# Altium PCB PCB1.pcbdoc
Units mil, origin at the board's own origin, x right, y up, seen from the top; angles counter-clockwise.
Board outline 5106.1 x 2904.45 mil, 2 copper layers (Top Layer, Bottom Layer); 73 components, 114 nets, 374 pads, 0 vias.
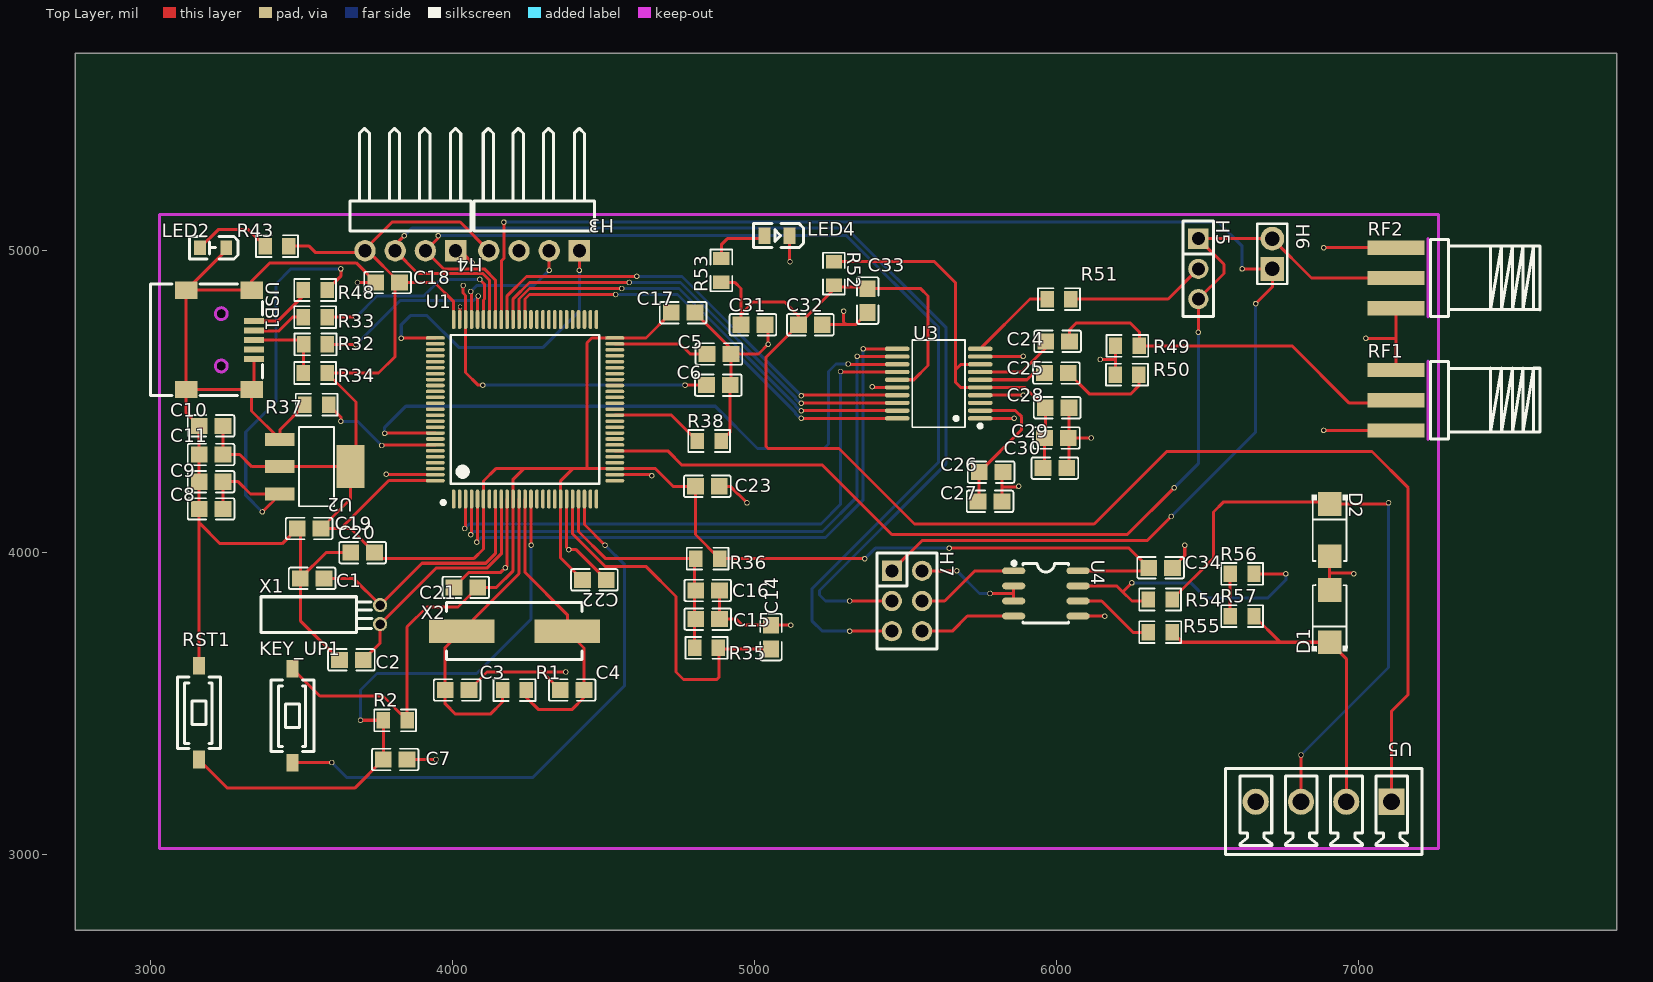
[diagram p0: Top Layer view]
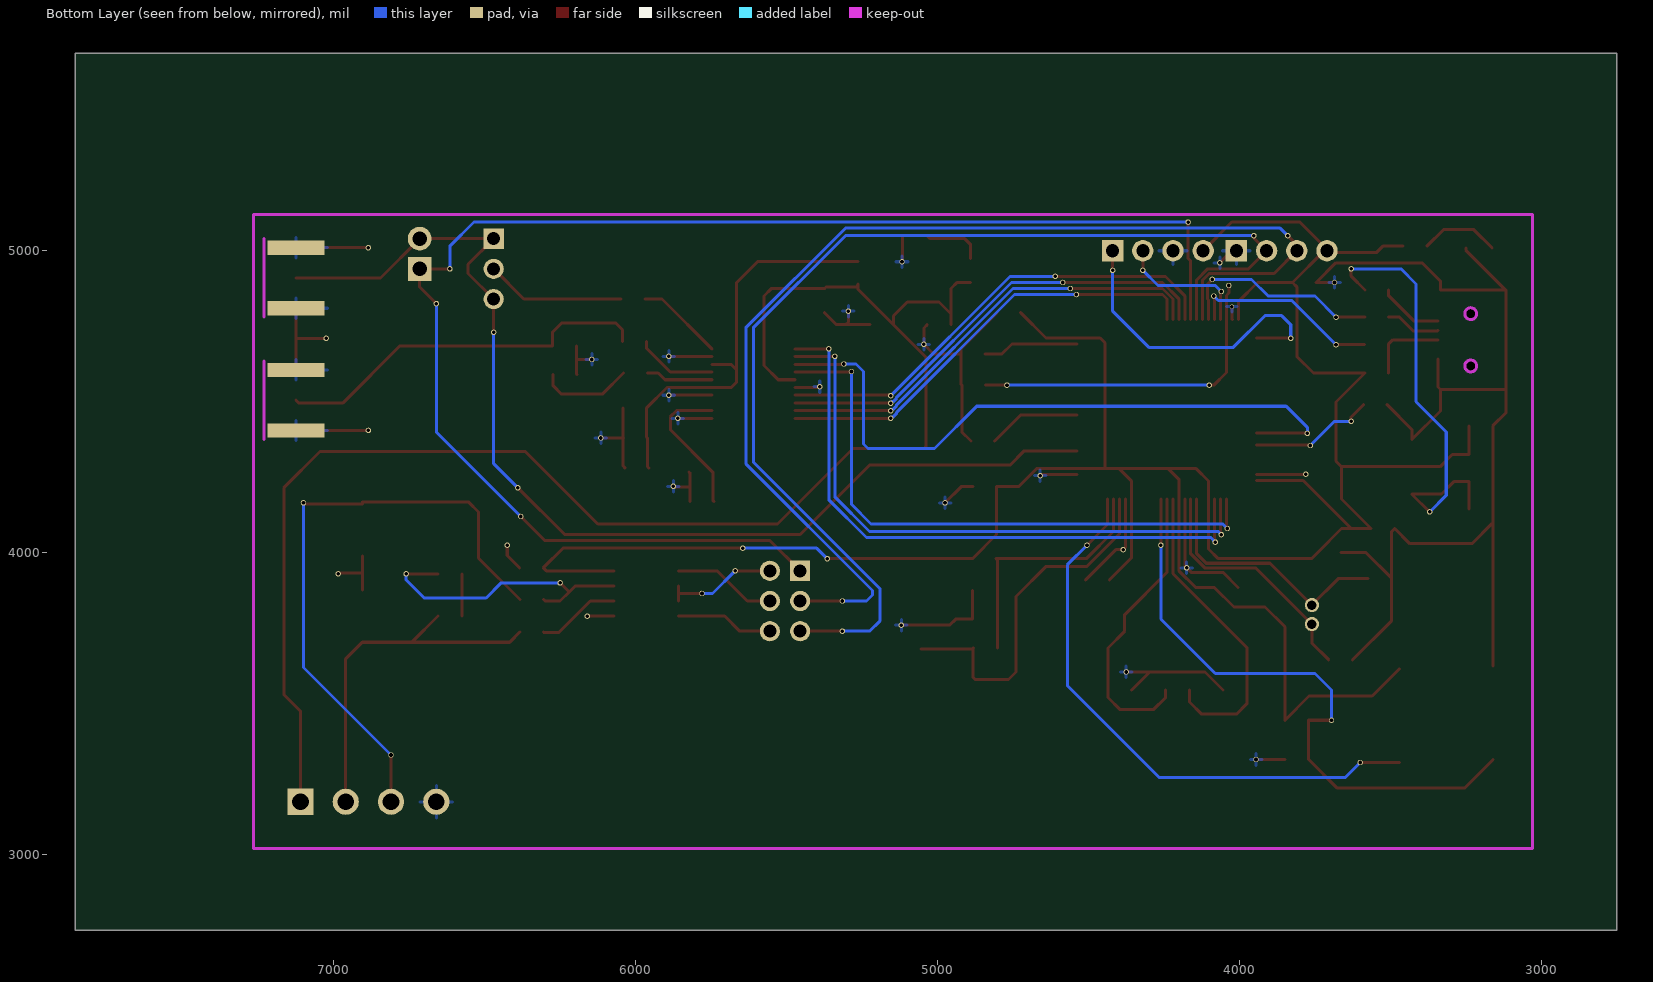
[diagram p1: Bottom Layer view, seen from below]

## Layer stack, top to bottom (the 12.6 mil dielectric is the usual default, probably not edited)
Top Layer: signal copper (thickness not stored)
Dielectric: dielectric 12.6, FR-4, Dk 4.8
Bottom Layer: signal copper (thickness not stored)

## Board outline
7856.1,2750 2750,2750 2750,5654.45 7856.1,5654.45

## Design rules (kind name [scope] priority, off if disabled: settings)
Clearance copperThickness1oz [All] p1: gap=7 ignorepadtopadclearanceinfootprint=FALSE except(4: Track-Track; 6: Track-SMDPad SMDPad-SMDPad Track-THPad SMDPad-THPad THPad-THPad Track-Via SMDPad-Via THPad-Via Via-Via SMDPad-Fill THPad-Fill Via-Fill Fill-Fill Track-Region SMDPad-Region THPad-Region Via-Region Region-Region Track-Poly SMDPad-Poly THPad-Poly Via-Poly Fill-Poly Region-Poly Poly-Poly Track-Text SMDPad-Text THPad-Text Via-Text Fill-Text Region-Text Poly-Text Text-Text; 6.9: Track-Hole SMDPad-Hole THPad-Hole Via-Hole Fill-Hole Region-Hole Poly-Hole Text-Hole Sheet-Hole; 11.8: Track-Fill Fill-Region Track-Sheet SMDPad-Sheet THPad-Sheet Via-Sheet Fill-Sheet Region-Sheet Poly-Sheet Text-Sheet)
Clearance copperThickness2oz [All] p1: gap=7 ignorepadtopadclearanceinfootprint=FALSE except(6: Track-SMDPad SMDPad-SMDPad Track-THPad SMDPad-THPad THPad-THPad Track-Via SMDPad-Via THPad-Via Via-Via SMDPad-Fill THPad-Fill Via-Fill Fill-Fill Track-Region SMDPad-Region THPad-Region Via-Region Region-Region Track-Poly SMDPad-Poly THPad-Poly Via-Poly Fill-Poly Region-Poly Poly-Poly Track-Text SMDPad-Text THPad-Text Via-Text Fill-Text Region-Text Poly-Text Text-Text; 6.9: Track-Hole SMDPad-Hole THPad-Hole Via-Hole Fill-Hole Region-Hole Poly-Hole Text-Hole Sheet-Hole; 8: Track-Track; 11.8: Track-Fill Fill-Region Track-Sheet SMDPad-Sheet THPad-Sheet Via-Sheet Fill-Sheet Region-Sheet Poly-Sheet Text-Sheet)
DiffPairsRouting differentialPair [All] p1: maxuncoupledlength=10 maxlimit=6 mostfreqgap=6 toplayer_minwidth=5 toplayer_prefwidth=10 toplayer_maxwidth=100 bottomlayer_minwidth=5 bottomlayer_prefwidth=10 bottomlayer_maxwidth=100
PasteMaskExpansion pasteMaskExpansion [All] p1:
PlaneConnect innerPlane [All] p1: planeconnectstyle=Relief reliefexpansion=20 reliefentries=4 reliefconductorwidth=10 reliefairgap=10
PolygonConnect copperRegion [All] p1: connectstyle=Relief reliefentries=4 reliefconductorwidth=10 polygonreliefangle="90 Angle" airgapwidth=10
RoutingVias viaSize [All] p1: viastyle="Through Hole" holewidth=12.0078 minholewidth=11.811 maxholewidth=248.0314 width=24.0158 minwidth=19.685 maxwidth=393.7008
SolderMaskExpansion solderMaskExpansion [All] p1: useseparateexpansions=TRUE expansion=2 expansionbottom=2
Width copperThickness1oz [All] p1: maxlimit=100 minlimit=5 preferedwidth=10
Width copperThickness2oz [All] p1: maxlimit=100 minlimit=8 preferedwidth=10

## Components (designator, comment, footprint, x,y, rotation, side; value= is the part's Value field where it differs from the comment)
C1 "CAP_0805" C0805 3534.99,3915 r0 top
C2 "CAP_0805" C0805 3664.99,3645 r0 top
C3 "CAP_0805" C0805 4014.99,3545 r0 top
C4 "CAP_0805" C0805 4396.26,3545 r180 top
C5 "CAP_0805" C0805 4882.4,4658.08 r0 top
C6 "CAP_0805" C0805 4879.99,4555 r0 top
C7 "CAP_0805" C0805 3809.99,3315 r180 top
C8 "CAP_0805" C0805 3199.99,4145 r0 top
C9 "CAP_0805" C0805 3199.99,4235 r0 top
C10 "CAP_0805" C0805 3199.99,4420 r0 top
C11 "CAP_0805" C0805 3199.99,4325 r0 top
C14 "CAP_0805" C0805 5054.36,3720.63 r90 top
C15 "CAP_0805" C0805 4844.99,3780 r0 top
C16 "CAP_0805" C0805 4844.99,3875 r0 top
C17 "CAP_0805" C0805 4763.73,4795 r180 top
C18 "CAP_0805" C0805 3784.99,4895 r0 top
C19 "CAP_0805" C0805 3524.99,4080 r0 top
C20 "CAP_0805" C0805 3702.12,4000.15 r0 top
C21 "CAP_0805" C0805 4043.74,3885 r0 top
C22 "CAP_0805" C0805 4469.99,3910 r180 top
C23 "CAP_0805" C0805 4843.73,4220 r180 top
C24 "CAP_0805" C0805 6003.73,4700 r180 top
C25 "CAP_0805" C0805 5999.99,4595 r180 top
C26 "CAP_0805" C0805 5783.52,4266.84 r0 top
C27 "CAP_0805" C0805 5779.99,4170 r0 top
C28 "CAP_0805" C0805 6002.48,4480 r0 top
C29 "CAP_0805" C0805 5999.99,4380 r0 top
C30 "CAP_0805" C0805 5994.99,4280 r0 top
C31 "CAP_0805" C0805 4994.99,4755 r0 top
C32 "CAP_0805" C0805 5184.99,4755 r0 top
C33 "CAP_0805" C0805 5374.99,4835 r270 top
C34 "CAP_0805" C0805 6344.99,3950 r0 top
D1 "M7_C95872" SMA_L4.3-W2.6-LS5.2-RD 6904.99,3790 r90 top
D2 "M7_C95872" SMA_L4.3-W2.6-LS5.2-RD 6904.99,4075 r270 top
H3 "2.54-1*4P反弯排针" HDR-TH_4P-P2.54-H-M-W10.4 4269.99,5000 r180 top
H4 "2.54-1*4P反弯排针" HDR-TH_4P-P2.54-H-M-W10.4 3859.99,5000 r180 top
H5 "PZ254V-11-03P" HDR-TH_3P-P2.54-V-M 6469.99,4940 r270 top
H6 "PZ254V-11-02P" HDR-TH_2P-P2.54-V-M 6714.99,4990 r90 top
H7 "PZ254V-12-6P" HDR-TH_6P-P2.54-V-M-R2-C3-S2.54 5504.99,3840 r270 top
KEY_UP1 "轻触按键3*6*2.5" SW-SMD_L6.0-W3.6-LS8.0 3469.99,3460 r270 top
LED2 "LED_0805-G" LED_0805 3204.99,5010 r180 top
LED4 "NCD0805R1" LED0805-R-RD 5074.99,5050 r180 top
R1 "Res_0805" R0805 4204.99,3545 r180 top
R2 "Res_0805" R0805 3809.99,3445 r0 top
R32 "Res_0805" R0805 3546.26,4690 r180 top
R33 "Res_0805" R0805 3544.99,4780 r0 top
R34 "Res_0805" R0805 3544.99,4595 r180 top
R35 "Res_0805" R0805 4841.26,3685 r180 top
R36 "Res_0805" R0805 4844.99,3980 r180 top
R37 "Res_0805" R0805 3549.99,4490 r180 top
R38 "Res_0805" R0805 4849.99,4370 r0 top
R43 "Res_0805" R0805 3418.74,5015 r180 top
R48 "Res_0805" R0805 3544.99,4870 r180 top
R49 "RC0805FR-0710KL" R0805 6234.99,4685 r0 top
R50 "RC0805FR-0710KL" R0805 6233.52,4589.88 r0 top
R51 "RC0805FR-0710KL" R0805 6008.73,4840 r180 top
R52 "RC0805FR-0710KL" R0805 5263.1,4924.37 r270 top
R53 "RC0805FR-0710KL" R0805 4889.99,4935 r90 top
R54 "RC0805FR-0710KL" R0805 6343.73,3845 r180 top
R55 "RC0805FR-0710KL" R0805 6343.82,3736.96 r0 top
R56 "RC0805FR-0710KL" R0805 6614.99,3930 r0 top
R57 "RC0805FR-0710KL" R0805 6614.99,3790 r0 top
RF1 "BWSMA-KE-P001" SMA-SMD_BWSMA-KE-P001 7124.99,4505 r0 top
RF2 "BWSMA-KE-P001" SMA-SMD_BWSMA-KE-P001 7124.99,4910 r0 top
RST1 "轻触按键3*6*2.5" SW-SMD_L6.0-W3.6-LS8.0 3159.99,3470 r270 top
U1 "STM32F407VET6" LQFP-100_L14.0-W14.0-P0.50-LS16.0-BL 4239.99,4475 r0 top
U2 "LM1117GS-ADJ" SOT-223-3_L6.5-W3.4-P2.30-LS7.0-BR 3544.99,4285 r180 top
U3 "AD9283BRSZ-100" SSOP-20_L7.2-W5.3-P0.65-LS7.8-BL 5609.99,4560 r90 top
U4 "SN65HVD72DR" SOIC-8_L5.0-W4.0-P1.27-LS6.0-BL 5964.99,3865 r270 top
U5 "691321300004" CONN-TH_4P-P3.81_691321300004 6884.99,3175 r180 top
USB1 "UX-144S-ACP5" MINI-USB-SMD_UX-144S-ACP5 3229.99,4705 r270 top
X1 "X308032768KGB2SC" OSC-TH_BD3.1-P0.8-D0.3 3759.99,3795 r0 top
X2 "X49SM8MSD2SC" CRYSTAL-SMD_L11.5-W4.8-LS12.7 4204.99,3740 r0 top

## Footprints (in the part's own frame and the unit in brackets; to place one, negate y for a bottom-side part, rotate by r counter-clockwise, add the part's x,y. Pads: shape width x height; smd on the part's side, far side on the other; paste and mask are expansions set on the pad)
C0805 [mm]
  rect 1.41x1.35 smd: 1(-1,0) 2(1,0)
  silkscreen extent -1.96,-0.9 1.96,0.9
CONN-TH_4P-P3.81_691321300004 [mm]
  rect 2.2x2.2 hole 1.4: 1(-5.715,0)
  round 2.2 hole 1.4: 2(-1.905,0) 3(1.905,0) 4(5.715,0)
  silkscreen extent -8.25,-2.79 8.25,4.45
CRYSTAL-SMD_L11.5-W4.8-LS12.7 [mm]
  rect 5.5x2 smd: 1(-4.45,0) 2(4.45,0)
  silkscreen extent -5.7,-2.4 5.7,2.4
HDR-TH_2P-P2.54-V-M [mm]
  rect 2x2 hole 1.2: 1(-1.27,0)
  round 2 hole 1.2: 2(1.27,0)
  silkscreen extent -2.54,-1.27 2.54,1.27
HDR-TH_3P-P2.54-V-M [mm]
  rect 1.7x1.7 hole 1.1: 1(-2.54,0)
  round 1.7 hole 1.1: 2(0,0) 3(2.54,0)
  silkscreen extent -4.02,-1.27 4.02,1.27
HDR-TH_4P-P2.54-H-M-W10.4 [mm]
  rect 1.8x1.8 hole 1.1: 1(-3.81,0)
  round 1.8 hole 1.1: 2(-1.27,0) 3(1.27,0) 4(3.81,0)
  silkscreen extent -5.09,-10.27 5.07,-1.65
HDR-TH_6P-P2.54-V-M-R2-C3-S2.54 [mm]
  rect 1.7x1.7 hole 1.1: 1(-2.54,-1.27)
  round 1.7 hole 1.1: 2(-2.54,1.27) 3(0,-1.27) 4(0,1.27) 5(2.54,-1.27) 6(2.54,1.27)
  silkscreen extent -4.04,-2.54 4.04,2.54
LED0805-R-RD [mm]
  rect 1x1.4 smd: 1(1.05,0) 2(-1.05,0)
  silkscreen extent -2.22,-1.04 1.99,1.01
LED_0805 [mm]
  rect 1x1.25 smd: 1(-1.15,0.005) 2(1.05,0.005)
  silkscreen extent -2.15,-0.94 1.93,0.97
LQFP-100_L14.0-W14.0-P0.50-LS16.0-BL [mm]
  oval 0.3x1.6 smd: 1(-6,-7.55) 2(-5.5,-7.55) 3(-5,-7.55) 4(-4.5,-7.55) 5(-4,-7.55) 6(-3.5,-7.55) 7(-3,-7.55) 8(-2.5,-7.55) 9(-2,-7.55) 10(-1.5,-7.55) 11(-1,-7.55) 12(-0.5,-7.55) 13(0,-7.55) 14(0.5,-7.55) 15(1,-7.55) 16(1.5,-7.55) 17(2,-7.55) 18(2.5,-7.55) 19(3,-7.55) 20(3.5,-7.55) 21(4,-7.55) 22(4.5,-7.55) 23(5,-7.55) 24(5.5,-7.55) 25(6,-7.55) 51(6,7.55) 52(5.5,7.55) 53(5,7.55) 54(4.5,7.55) 55(4,7.55) 56(3.5,7.55) 57(3,7.55) 58(2.5,7.55) 59(2,7.55) 60(1.5,7.55) 61(1,7.55) 62(0.5,7.55) 63(0,7.55) 64(-0.5,7.55) 65(-1,7.55) 66(-1.5,7.55) 67(-2,7.55) 68(-2.5,7.55) 69(-3,7.55) 70(-3.5,7.55) 71(-4,7.55) 72(-4.5,7.55) 73(-5,7.55) 74(-5.5,7.55) 75(-6,7.55)
  oval 1.6x0.3 smd: 26(7.55,-6) 27(7.55,-5.5) 28(7.55,-5) 29(7.55,-4.5) 30(7.55,-4) 31(7.55,-3.5) 32(7.55,-3) 33(7.55,-2.5) 34(7.55,-2) 35(7.55,-1.5) 36(7.55,-1) 37(7.55,-0.5) 38(7.55,0) 39(7.55,0.5) 40(7.55,1) 41(7.55,1.5) 42(7.55,2) 43(7.55,2.5) 44(7.55,3) 45(7.55,3.5) 46(7.55,4) 47(7.55,4.5) 48(7.55,5) 49(7.55,5.5) 50(7.55,6) 76(-7.55,6) 77(-7.55,5.5) 78(-7.55,5) 79(-7.55,4.5) 80(-7.55,4) 81(-7.55,3.5) 82(-7.55,3) 83(-7.55,2.5) 84(-7.55,2) 85(-7.55,1.5) 86(-7.55,1) 87(-7.55,0.5) 88(-7.55,0) 89(-7.55,-0.5) 90(-7.55,-1) 91(-7.55,-1.5) 92(-7.55,-2) 93(-7.55,-2.5) 94(-7.55,-3) 95(-7.55,-3.5) 96(-7.55,-4) 97(-7.55,-4.5) 98(-7.55,-5) 99(-7.55,-5.5) 100(-7.55,-6)
  silkscreen extent -7.03,-8 6.25,6.25
MINI-USB-SMD_UX-144S-ACP5 [mm]
  rect 0.5x1.7 smd: 1(-1.6,2.85) 2(-0.8,2.85) 3(0,2.85) 4(0.8,2.85) 5(1.6,2.85)
  rect 1.45x1.9 smd: 6(-4.175,2.65) 7(-4.175,-2.85) 8(4.175,-2.85) 9(4.175,2.65)
  Multi-Layer board cut-out: -2.2,0.6 -2.447,0.53 -2.626,0.348 -2.692,0.1 -2.626,-0.148 -2.447,-0.33 -2.2,-0.4 -2.2,-0.4 -1.953,-0.33 -1.774,-0.148 -1.708,0.1 -1.774,0.348 -1.953,0.53 -2.2,0.6
  Multi-Layer board cut-out: 2.2,0.6 1.954,0.53 1.774,0.348 1.708,0.1 1.774,-0.148 1.954,-0.33 2.2,-0.4 2.2,-0.4 2.447,-0.33 2.627,-0.148 2.692,0.1 2.627,0.348 2.447,0.53 2.2,0.6
  Multi-Layer keep-out circle w0.254: c-2.2,0.1 r0.5
  Multi-Layer keep-out circle w0.254: c2.2,0.1 r0.5
  silkscreen extent -4.7,-5.84 4.7,3.56
OSC-TH_BD3.1-P0.8-D0.3 [mm]
  round 1.2 hole 0.8: 1(0,0.8) 2(0,-0.8)
  silkscreen extent -10,-1.5 -0.7,1.5
R0805 [mm]
  rect 1.133x1.377 smd: 1(-1,0) 2(1,0)
  silkscreen extent -1.76,-0.92 1.76,0.92
SMA-SMD_BWSMA-KE-P001 [mm]
  rect 4.8x1.2 smd: 1(0,-2.55) 2(0,2.55) 5(0,0)
  rect 4.8x1.2 smd far side: 3(0,2.55) 4(0,-2.55)
  Board Outline Layer lines w0.254: 2.7,-3.3 2.7,3.3 2.7,-3.3
  silkscreen extent 2.89,-3.25 12.1,3.25
SMA_L4.3-W2.6-LS5.2-RD [mm]
  rect 2x2 smd: 1(-2.2,0) 2(2.2,0)
  silkscreen extent -2.98,-1.5 2.6,1.5
SOIC-8_L5.0-W4.0-P1.27-LS6.0-BL [mil]
  oval 22.38x76.78 smd: 1(-75,-106.5) 2(-25,-106.5) 3(25,-106.5) 4(75,-106.5) 5(75,106.5) 6(25,106.5) 7(-25,106.5) 8(-75,106.5)
  silkscreen extent -106,-111 98,75
SOT-223-3_L6.5-W3.4-P2.30-LS7.0-BR [mm]
  rect 2.5x1.1 smd: 1(2.97,-2.3) 2(2.97,0) 3(2.97,2.3)
  rect 2.34x3.6 smd: 4(-2.97,0)
  silkscreen extent -1.57,-3.33 1.37,3.33
SSOP-20_L7.2-W5.3-P0.65-LS7.8-BL [mil]
  oval 14.33x81.97 smd: 1(-115.16,-137.44) 2(-89.57,-137.44) 3(-63.98,-137.44) 4(-38.39,-137.44) 5(-12.79,-137.44) 6(12.8,-137.44) 7(38.39,-137.44) 8(63.98,-137.44) 9(89.57,-137.44) 10(115.16,-137.44) 11(115.16,137.44) 12(89.57,137.44) 13(63.98,137.44) 14(38.39,137.44) 15(12.8,137.44) 16(-12.79,137.44) 17(-38.39,137.44) 18(-63.98,137.44) 19(-89.57,137.44) 20(-115.16,137.44)
  silkscreen extent -146,-143 145,87
SW-SMD_L6.0-W3.6-LS8.0 [mm]
  rect 1.5x1 smd: 1(-3.95,0) 2(3.95,0)
  silkscreen extent -3,-1.8 3,1.8

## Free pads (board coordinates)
  round 18 hole 12: 1(3369.99,4135) 1(3599.99,3305) 1(3629.99,4435) 1(3629.99,4940) 1(3679.99,4780) 1(3684.99,4895) 1(3694.99,3445) 1(3774.99,4395) 1(3779.99,4260) 1(3829.99,4710) 1(3839.99,5050) 1(3944.99,3315) 1(4034.99,4885) 1(4039.99,4080) 1(4059.99,4060) 1(4059.99,4865) 1(4064.99,4960) 1(4079.99,4035) 1(4084.99,4850) 1(4099.99,4555) 1(4169.99,5095) 1(4174.99,3950) 1(4259.99,4025) 1(4319.99,4935) 1(4374.99,3605) 1(4384.99,4010) 1(4539.99,4855) 1(4559.99,4875) 1(4584.99,4895) 1(4609.99,4915) 1(4659.99,4255) 1(4974.99,4165) 1(5044.99,4690) 1(5117.55,4963.61) 1(5119.99,3760) 1(5154.99,4445) 1(5154.99,4470) 1(5154.99,4495) 1(5154.99,4520) 1(5284.99,4600) 1(5294.99,4800) 1(5309.99,4625) 1(5314.99,3840) 1(5339.99,4650) 1(5359.99,4675) 1(5389.99,4550) 1(5644.99,4015) 1(5669.99,3940) 1(5859.99,4445) 1(5874.99,4220) 1(5889.56,4521.45) 1(5889.99,4650) 1(6114.99,4380) 1(6144.99,4640) 1(6159.99,3790) 1(6379.99,4120) 1(6389.99,4215) 1(6424.99,4025) 1(6469.99,4730) 1(6614.99,4940) 1(6759.99,3930) 1(6884.99,5010) 1(6984.99,3930) 1(7099.99,4165) 2(3679.99,4688.47) 2(3764.99,4355) 2(3952.14,5050) 2(4089.99,4905) 2(4419.99,4935) 2(4504.99,4025) 2(4769.99,4555) 2(5314.99,3740) 2(5364.99,3980) 2(5779.99,3865) 2(6249.99,3900) 2(6659.99,4825) 2(6809.99,3330) 2(7024.99,4710) 3(6884.99,4405)
  round 14 hole 12: 1(4024.99,4815)

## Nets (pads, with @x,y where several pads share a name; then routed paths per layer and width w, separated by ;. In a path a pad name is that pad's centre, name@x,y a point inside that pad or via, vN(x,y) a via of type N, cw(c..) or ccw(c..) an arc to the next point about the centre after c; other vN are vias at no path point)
3V3: C10.2 C11.2 C17.2 C18.2 C19.2 C20.2 C21.2 C22.2 C23.2 C34.1 H3.4 H4.4 KEY_UP1.1 pad.1@5644.99,4015 pad.2@5364.99,3980 R2.2 R34.1 R36.1 R43.1 U1.6 U1.11 U1.19 U1.28 U1.50 U1.75 U1.100 U2.2 U2.4 U4.8 | length 9419.8
  Top Layer w10: C10.2 C11.2 3294.99,4325 3334.99,4285 U2.2 U2.4 ; R43.1 3524.99,5015 3544.99,4995 3704.99,4995 H4.4 ; KEY_UP1.1 3560.51,3525 3769.36,3525 R2.2 3849.36,3754.37 3914.99,3820 4018.11,3820 C21.2 4144.99,3885 4200.62,3940.63 U1.11 4200.62,4243.45 4235.33,4278.15 ; U1.100 3788.78,4238.78 3629.99,4080 ; U1.75 4003.78,4831.22 3939.99,4895 C18.2 ; H3.4 4024.99,5095 3799.99,5095 3709.99,5005 H4.4 ; C22.2 4358.1,3982.52 U1.19 4358.1,4238.11 4398.15,4278.15 ; C17.2 4640.59,4711.22 U1.50 4461.22,4711.22 4444.99,4695 4444.99,4282.35 4440.8,4278.15 ; pad.2@5364.99,3980 R36.1 4804.36,4060 C23.2 4729.99,4220 4671.85,4278.15 U1.28 4440.8,4278.15 ; pad.1@5644.99,4015 6240.62,4015 C34.1 6295.62,3940 U4.8 ; 3629.99,4080 C19.2 3661.92,4177.56 U2.4 ; 3629.99,4080 3661.64,4080 C20.2 3761.64,3980 4069.99,3980 4102.19,4012.2 U1.6 4102.19,4237.2 4143.15,4278.15 4235.33,4278.15 ; U2.4 3679.99,4303.07 3679.99,4499.37 R34.1 3754.99,4595 3809.99,4650 3809.99,4880.63 C18.2 ; H4.4 3719.36,5000 C18.2 ; 4235.33,4278.15 4398.15,4278.15 ; 4398.15,4278.15 4440.8,4278.15
  Bottom Layer w10: pad.2@5364.99,3980 5399.99,4015 pad.1@5644.99,4015
5V: C8.2 C9.2 pad.1@3369.99,4135 pad.1@3629.99,4940 R48.1 U2.3 | length 1522.8
  Top Layer w10: C8.2 C9.2 3289.99,4235 3330.55,4194.45 U2.3 3428.07,4193.07 pad.1@3369.99,4135 ; R48.1 3629.99,4915.63 pad.1@3629.99,4940
  Bottom Layer w10: pad.1@3369.99,4135 3314.99,4190 3314.99,4400 3414.99,4500 3414.99,4890 3464.99,4940 pad.1@3629.99,4940
$1N4807: C3.1 R1.2 U1.12 X2.1 | length 1040.2
  Top Layer w10: R1.2 4165.62,3505.63 4124.99,3465 4009.99,3465 3975.62,3499.37 C3.1 3975.62,3685.83 X2.1 4220.31,3930.52 U1.12
$1N4812: C5.1 U1.49 | length 319.7
  Top Layer w10: U1.49 4753.45,4691.54 4786.92,4658.08 C5.1
$1N4813: C6.1 pad.1@4034.99,4885 pad.1@4099.99,4555 pad.2@4769.99,4555 U1.73 | length 1106.3
  Top Layer w10: pad.1@4034.99,4885 4034.99,4860 4043.14,4851.85 U1.73 4043.14,4596.85 4084.99,4555 pad.1@4099.99,4555 ; pad.2@4769.99,4555 C6.1
  Bottom Layer w10: pad.1@4099.99,4555 pad.2@4769.99,4555
$1N4821: R33.1 USB1.2 | length 182.7
  Top Layer w10: USB1.2 3343.69,4735 3424.99,4735 3469.99,4780 R33.1
$1N4826: R32.2 R34.2 USB1.3 | length 266.4
  Top Layer w10: USB1.3 3491.89,4705 R32.2 3506.89,4596.26 R34.2
$1N4854: C4.1 R1.1 U1.13 X2.2 | length 987.5
  Top Layer w10: U1.13 4239.99,3935 4380.19,3794.8 X2.2 4435.62,3684.57 C4.1 4435.62,3520.63 4394.99,3480 4284.99,3480 4244.36,3520.63 R1.1
$1N5000: LED2.2 R43.2 | length 263.4
  Top Layer w10: LED2.2 3223.86,5070 3324.36,5070 R43.2
$1N5174: R48.2 USB1.1 | length 217
  Top Layer w10: USB1.1 3422.99,4767.99 3505.62,4850.63 R48.2
$1N5977: C24.1 R49.2 RF1.5 | length 1269.7
  Top Layer w10: C24.1 6043.1,4738.11 6064.99,4760 6244.99,4760 6274.36,4730.63 R49.2 6779.99,4685 6969.99,4495 7114.99,4495 RF1.5
$1N6051: C25.2 U3.6 | length 222.4
  Top Layer w10: U3.6 5902.8,4572.8 5924.99,4595 C25.2
$1N6099: C24.2 U3.7 | length 272
  Top Layer w10: U3.7 5884.99,4598.39 5964.36,4677.76 C24.2
$1N6101: C25.1 R50.2 | length 311.1
  Top Layer w10: C25.1 6039.99,4595 6109.99,4525 6244.99,4525 6272.89,4552.9 R50.2
$1N6148: R51.2 U3.10 | length 290.2
  Top Layer w10: U3.10 5912.27,4840 R51.2
$1N6271: U3.3
$1N6372: C26.1 C27.1 U3.2 | length 485.8
  Top Layer w10: C27.1 5744.15,4173.53 C26.1 5884.99,4407.68 5884.99,4450 5864.56,4470.43 U3.2
$1N6529: C28.1 C29.1 C30.1 R52.1 U3.5 U3.8 | length 1387.1
  Top Layer w10: R52.1 5596.26,4963.74 5664.99,4895 5664.99,4605 ; U3.8 5683.98,4623.98 5664.99,4605 ; C30.1 5960.62,4285 C29.1 5963.1,4382.48 C28.1 5895.9,4547.21 U3.5 5682.78,4547.21 5664.99,4565 5664.99,4605
$1N7135: LED4.1 R53.2 | length 201.7
  Top Layer w10: R53.2 4889.99,5020 4909.99,5040 5023.65,5040 LED4.1
$1N7463: H5.2 R51.1 | length 463.3
  Top Layer w10: R51.1 6369.99,4840 H5.2
$1N8489: pad.1@6759.99,3930 pad.2@6249.99,3900 R54.2 R56.2 U4.7 | length 979.3
  Top Layer w10: U4.7 6199.99,3890 6219.89,3870.11 ; pad.2@6249.99,3900 6220.1,3870.11 6219.89,3870.11 ; R54.2 6299.36,3840 6249.99,3840 6219.89,3870.11 ; R56.2 pad.1@6759.99,3930
  Bottom Layer w10: pad.2@6249.99,3900 6444.99,3900 6494.99,3850 6699.99,3850 6759.99,3910 pad.1@6759.99,3930
$1N8493: R55.1 U4.6 | length 277.3
  Top Layer w10: U4.6 6149.99,3840 6254.99,3735 6302.5,3735 R55.1
$1N8582: D1.1 R55.2 R57.2 U5.2 | length 1209.4
  Top Layer w10: R55.2 6416.76,3703.39 6740.98,3703.39 ; R57.2 6740.98,3703.39 ; U5.2 6959.99,3648.39 D1.1 6740.98,3703.39
$1N8624: R56.1 R57.1 | length 140
  Top Layer w10: R57.1 R56.1
$1N8798: D2.1 pad.1@7099.99,4165 pad.2@6809.99,3330 R54.1 U5.3 | length 2052.1
  Top Layer w10: R54.1 6519.99,3981.89 6519.99,4135 6552.49,4167.5 6904.1,4167.5 D2.1@6904.99,4166.61 ; U5.3 pad.2@6809.99,3329.99 ; D2.1 7096.6,4161.61 pad.1@7099.99,4165
  Bottom Layer w10: pad.2@6809.99,3330 7099.99,3620 pad.1@7099.99,4165
+5V: C31.1 C32.1 C33.1 R52.2 R53.1 U3.15 U5.1 | length 5237.8
  Top Layer w10: R53.1 4934.36,4895.63 4954.99,4875 4954.99,4755.63 C31.1 4955.62,4790.63 4994.99,4830 5099.99,4830 5145.62,4784.37 C32.1 ; R52.2 5263.1,4872.48 C32.1 ; R52.2@5263.1,4890 5263.1,4887.07 5270.18,4880 5369.36,4880 C33.1 5550.62,4874.37 5574.99,4850 5574.99,4620 5527.8,4572.8 U3.15 ; U5.1 7109.99,3474.99 7164.99,3530 7164.99,4215 7044.99,4335 6364.99,4335 6124.99,4095 5529.99,4095 5279.99,4345 5044.99,4345 5037.92,4352.07 5037.92,4647.3 C32.1
BOOT0: 
F_CS: U1.35
FSMC_A18: U1.60
FSMC_D0: U1.61
FSMC_D1: U1.62
FSMC_D2: U1.81
FSMC_D3: U1.82
FSMC_D4: U1.38
FSMC_D5: U1.39
FSMC_D6: U1.40
FSMC_D7: U1.41
FSMC_D8: U1.42
FSMC_D9: U1.43
FSMC_D10: U1.44
FSMC_D11: U1.45
FSMC_D12: U1.46
FSMC_D13: U1.55
FSMC_D14: U1.56
FSMC_D15: U1.57
FSMC_NE1: U1.88
FSMC_NOE: U1.85
FSMC_NWE: U1.86
GND: C1.1 C2.1 C3.2 C4.2 C5.2 C6.2 C7.1 C8.1 C9.1 C10.1 C11.1 C14.2 C15.2 C16.2 C17.1 C18.1 C19.1 C20.1 C21.1 C22.1 C23.1 C26.2 C27.2 C28.2 C29.2 C30.2 C31.2 C32.2 C33.2 C34.2 D1.2 D2.2 H3.3 H4.1 LED2.1 LED4.2 pad.1@3684.99,4895 pad.1@3779.99,4260 pad.1@3944.99,3315 pad.1@4024.99,4815 pad.1@4064.99,4960 pad.1@4174.99,3950 pad.1@4374.99,3605 pad.1@4384.99,4010 pad.1@4659.99,4255 pad.1@4974.99,4165 pad.1@5044.99,4690 pad.1@5117.55,4963.61 pad.1@5119.99,3760 pad.1@5294.99,4800 pad.1@5389.99,4550 pad.1@5859.99,4445 pad.1@5874.99,4220 pad.1@5889.56,4521.45 pad.1@5889.99,4650 pad.1@6114.99,4380 pad.1@6144.99,4640 pad.1@6159.99,3790 pad.1@6424.99,4025 pad.1@6884.99,5010 pad.1@6984.99,3930 pad.2@7024.99,4710 pad.3 R37.2 R38.2 R49.1 R50.1 RF1.1 RF1.2 RF1.3 RF1.4 RF2.1 RF2.2 RF2.3 RF2.4 RST1.1 U1.10 U1.20 U1.27 U1.74 U1.99 U2.1 U3.1 U3.4 U3.9 U3.16 U4.5 U5.4 USB1.5 USB1.6 USB1.7 USB1.8 USB1.9 | length 9332.2
  Top Layer w10: RST1.1 3160.62,3626.14 3160.62,4096.11 ; LED2.1 3250.28,5001.86 USB1.7 ; USB1.5 3342.2,4548.5 USB1.9 ; R37.2 3428.07,4407.44 U2.1 3334.33,4469.29 USB1.9 ; C2.1 3495.62,3775 C1.1 ; C20.1 3580.78,4000.15 C1.1 ; pad.1@3684.99,4895 C18.1 3680.62,4960 3394.99,4960 3334.33,4899.34 USB1.6 USB1.7 ; pad.1@3779.99,4260 3781.53,4258.46 U1.99 ; C7.1 pad.1@3944.99,3315 ; C21.1 4054.36,3935 4159.99,3935 4174.99,3950 4180.94,3955.94 U1.10 ; H4.1 4024.99,5000 pad.1@4064.99,4960 ; U1.74 4024.99,4773.78 pad.1@4024.99,4815 ; C3.2 4114.36,3605 4296.89,3605 ; C4.2 4296.89,3605 ; pad.1@4374.99,3605 4296.89,3605 ; U1.20 4377.8,4017.2 4384.99,4010 4409.36,4010 C22.1 ; U1.27 4656.53,4258.46 pad.1@4659.99,4255 ; C17.1 4921.77,4676.34 C5.2 ; C23.1 4919.99,4220 pad.1@4974.99,4165 ; C16.2 C15.2 4939.99,3780 4959.99,3760 C14.2 pad.1@5119.99,3760 ; R38.2 4919.36,4400 C6.2 4921.77,4557.4 C5.2 ; C31.2 5044.99,4744.37 5044.99,4690 5013.07,4658.08 C5.2 ; LED4.2 5116.35,4964.81 pad.1@5117.55,4963.61 ; C32.2 5303.57,4755 ; pad.1@5294.99,4800 5294.99,4763.58 5303.57,4755 ; C33.2 5334.36,4755 5303.57,4755 ; pad.1@5389.99,4550 5392.78,4547.21 U3.16 ; U3.1 5859.84,4444.84 pad.1@5859.99,4445 ; U3.4 5889.4,4521.61 pad.1@5889.56,4521.45 ; U3.9 5889.56,4649.57 pad.1@5889.99,4650 ; C27.2 5819.36,4217.94 ; C26.2 5819.36,4263.31 5819.36,4217.94 ; pad.1@5874.99,4220 5872.94,4217.94 5819.36,4217.94 ; C30.2 6041.85,4287.48 C29.2@6041.85,4380 ; C29.2 C29.2@6041.85,4380 ; C28.2 C29.2@6041.85,4380 ; U4.5 pad.1@6159.99,3790 ; pad.1@6114.99,4380 C29.2@6041.85,4380 ; pad.1@6144.99,4640 6193.94,4640 6195.62,4638.31 ; R50.1 6195.62,4591.35 6195.62,4638.31 ; R49.1 6195.62,4638.31 ; C34.2 6424.99,3990.63 pad.1@6424.99,4025 ; pad.3 7124.61,4405 RF1.1 ; pad.1@6884.99,5010 7124.6,5010 RF2.2 ; D1.2 6904.99,3931.98 ; D2.2 6904.99,3931.98 ; pad.1@6984.99,3930 6983.02,3931.98 6904.99,3931.98 ; pad.2@7024.99,4710 7124.49,4710 7125,4709.49 ; RF1.2 7125,4709.49 ; RF2.1 7125,4709.49 ; USB1.8 USB1.7 ; USB1.8 USB1.9 ; USB1.8 3117.79,4462.84 C10.1 C11.1 C9.1 C8.1 3160.62,4096.11 ; 3160.62,4096.11 3163.89,4096.11 3229.99,4030 3435.62,4030 C19.1 3495.62,4070 C1.1
LCD_BL: U1.36
PA0/WK_UP: KEY_UP1.2 pad.1@3599.99,3305 pad.2@4504.99,4025 U1.23 | length 1920.2
  Top Layer w10: KEY_UP1.2 3599.49,3304.49 pad.1@3599.99,3305 ; U1.23 4436.85,4093.15 pad.2@4504.99,4025
  Bottom Layer w10: pad.1@3599.99,3305 3649.99,3255 4264.99,3255 4569.99,3560 4569.99,3960 pad.2@4504.99,4025
PA1: U1.24
PA2: U1.25
PA3: U1.26
PA4: U1.29
PA5: U1.30
PA6: H5.1 H5.3 H6.2 pad.1@6389.99,4215 pad.1@6469.99,4730 RF2.5 U1.31 | length 3669.2
  Top Layer w10: U1.31 4712.8,4337.2 4759.99,4290 5224.99,4290 5454.99,4060 6234.99,4060 pad.1@6389.99,4215 ; pad.1@6469.99,4730 H5.3 6554.99,4925 6554.99,4955 H5.1 H6.2 6844.99,4910.01 RF2.5
  Bottom Layer w10: pad.1@6389.99,4215 6469.99,4295 pad.1@6469.99,4730
PA7: U1.32
PA8: H6.1 H7.1 pad.1@4169.99,5095 pad.1@6379.99,4120 pad.1@6614.99,4940 pad.2@6659.99,4825 U1.67 | length 4937.8
  Top Layer w10: U1.67 4161.26,4966.26 4169.99,4975 pad.1@4169.99,5095 ; H7.1 5554.99,4040 6299.99,4040 pad.1@6379.99,4120 ; pad.1@6614.99,4940 H6.1 6714.99,4880 pad.2@6659.99,4825
  Bottom Layer w10: pad.1@4169.99,5095 6534.99,5095 6614.99,5015 pad.1@6614.99,4940 ; pad.1@6379.99,4120 6659.99,4400 pad.2@6659.99,4825
PA9/TXD1: H4.2 H7.5 pad.2@3952.14,5050 pad.2@5314.99,3740 U1.68 | length 3677.9
  Top Layer w10: pad.2@3952.14,5050 3952.14,5042.15 H4.2 3969.99,4940 4104.99,4940 4141.56,4903.43 U1.68 ; pad.2@5314.99,3740 H7.5
  Bottom Layer w10: pad.2@3952.14,5050 5304.99,5050 5609.99,4745 5609.99,4300 5189.99,3880 5189.99,3775 5224.99,3740 pad.2@5314.99,3740
PA10/RXD1: H4.3 H7.3 pad.1@3839.99,5050 pad.1@5314.99,3840 U1.69 | length 3794.6
  Top Layer w10: pad.1@3839.99,5050 3809.99,5020 H4.3 3884.99,4925 4099.99,4925 4121.89,4903.11 U1.69 ; pad.1@5314.99,3840 H7.3
  Bottom Layer w10: pad.1@3839.99,5050 3864.99,5075 5304.99,5075 5634.99,4745 5634.99,4295 5214.99,3875 5214.99,3860 5234.99,3840 pad.1@5314.99,3840
PA11/USB_DM: pad.1@3679.99,4780 pad.2@4089.99,4905 R33.2 U1.70 | length 697.5
  Top Layer w10: R33.2 pad.1@3679.99,4780 ; pad.2@4089.99,4905 4104.99,4890 4104.99,4840 4102.19,4837.2 U1.70
  Bottom Layer w10: pad.1@3679.99,4780 3749.99,4850 3904.99,4850 3959.99,4905 pad.2@4089.99,4905
PA12/USB_DP: pad.1@4084.99,4850 pad.2@3679.99,4688.47 R32.1 U1.71 | length 645.7
  Top Layer w10: R32.1 3678.47,4690 pad.2@3679.99,4688.47 ; U1.71 4082.51,4847.52 pad.1@4084.99,4850
  Bottom Layer w10: pad.2@3679.99,4688.47 3826.52,4835 4069.99,4835 pad.1@4084.99,4850
PA13/TMS: H3.2 pad.1@4059.99,4865 pad.1@4319.99,4935 U1.72 | length 447.9
  Top Layer w10: pad.1@4059.99,4865 4062.82,4862.17 U1.72 ; pad.1@4319.99,4935 H3.2
  Bottom Layer w10: pad.1@4059.99,4865 4079.99,4885 4269.99,4885 pad.1@4319.99,4935
PA14/TCK: H3.1 pad.1@3829.99,4710 pad.2@4419.99,4935 U1.76 | length 1053.9
  Top Layer w10: pad.1@3829.99,4710 3831.22,4711.22 U1.76 ; pad.2@4419.99,4935 H3.1
  Bottom Layer w10: pad.1@3829.99,4710 3829.99,4755 3859.99,4785 3914.99,4785 4019.99,4680 4299.99,4680 4419.99,4800 pad.2@4419.99,4935
PA15/TDI: U1.77
PB2/BOOT1: R38.1 U1.37 | length 308.7
  Top Layer w10: U1.37 4725.31,4455.32 R38.1
PB3/TDO: U1.89
PB4/TRST: U1.90
PB5: U1.91
PB6: pad.1@3774.99,4395 pad.1@5309.99,4625 U1.92 U3.13 | length 2229.8
  Top Layer w10: pad.1@3774.99,4395 3776.26,4396.26 U1.92 ; pad.1@5309.99,4625 5311.02,4623.98 U3.13
  Bottom Layer w10: pad.1@3774.99,4395 3774.99,4415 3844.99,4485 4869.99,4485 5009.99,4345 5229.99,4345 5244.99,4360 5244.99,4600 5269.99,4625 pad.1@5309.99,4625
PB7: U1.93
PB8: U1.95
PB9: U1.96
PB10: U1.47
PB11: U1.48
PB12: U1.51
PB13: U1.52
PB14: U1.53
PB15: U1.54
PC0: U1.15
PC1: U1.16
PC2: U1.17
PC3: U1.18
PC4: U1.33
PC5: U1.34
PC6: pad.1@4539.99,4855 pad.1@5154.99,4445 U1.63 U3.20 | length 1478.3
  Top Layer w10: U1.63 4239.99,4840 4254.99,4855 pad.1@4539.99,4855 ; pad.1@5154.99,4445 5155.15,4444.84 U3.20
  Bottom Layer w10: pad.1@4539.99,4855 4744.99,4855 5135.01,4464.98 5135.01,4461.72 5146.72,4450.02 5149.98,4450.02 pad.1@5154.99,4445
PC7: pad.1@4559.99,4875 pad.1@5154.99,4470 U1.64 U3.19 | length 1504.8
  Top Layer w10: U1.64 4219.99,4772.56 4219.99,4840 4254.99,4875 pad.1@4559.99,4875 ; pad.1@5154.99,4470 5155.43,4470.43 U3.19
  Bottom Layer w10: pad.1@4559.99,4875 4749.99,4875 5135.01,4489.98 5135.01,4486.72 5146.72,4475.02 5149.98,4475.02 pad.1@5154.99,4470
PC8: pad.1@4584.99,4895 pad.1@5154.99,4495 U1.65 U3.18 | length 1530.9
  Top Layer w10: U1.65 4200.62,4840.63 4254.99,4895 pad.1@4584.99,4895 ; pad.1@5154.99,4495 5156.02,4496.02 U3.18
  Bottom Layer w10: pad.1@4584.99,4895 4754.99,4895 5135.01,4514.98 5135.01,4511.72 5146.72,4500.02 5149.98,4500.02 pad.1@5154.99,4495
PC9: pad.1@4609.99,4915 pad.1@5154.99,4520 U1.66 U3.17 | length 1561.1
  Top Layer w10: U1.66 4180.94,4850.94 4244.99,4915 pad.1@4609.99,4915 ; pad.1@5154.99,4520 5156.6,4521.61 U3.17
  Bottom Layer w10: pad.1@4609.99,4915 4759.99,4915 pad.1@5154.99,4520
PC10: U1.78
PC11: U1.79
PC12: U1.80
PC13: U1.7
PC14: C1.2 U1.8 X1.1 | length 855.5
  Top Layer w10: C1.2 3671.49,3915 X1.1 3898.5,3965 4109.99,3965 4141.56,3996.57 U1.8
PC15: C2.2 U1.9 X1.2 | length 820.7
  Top Layer w10: C2.2 3760,3700.63 X1.2 3946.5,3950 4114.99,3950 4161.26,3996.26 U1.9
PD2: U1.83
PD3: U1.84
PD6: U1.87
PD11: U1.58
PD12: U1.59
PE0: U1.97
PE1: U1.98
PE2: U1.1
PE3: U1.2
PE4: pad.1@4039.99,4080 pad.1@5284.99,4600 U1.3 U3.14 | length 2005.4
  Top Layer w10: pad.1@4039.99,4080 4043.14,4083.15 U1.3 ; pad.1@5284.99,4600 5286.6,4598.39 U3.14
  Bottom Layer w10: pad.1@4039.99,4080 4054.99,4095 5219.99,4095 5284.99,4160 pad.1@5284.99,4600
PE5: pad.1@4059.99,4060 pad.1@5339.99,4650 U1.4 U3.12 | length 2048.4
  Top Layer w10: pad.1@4059.99,4060 4062.82,4062.83 U1.4 ; pad.1@5339.99,4650 5472.12,4650 U3.12
  Bottom Layer w10: pad.1@4059.99,4060 4069.99,4070 5224.99,4070 5339.99,4185 pad.1@5339.99,4650
PE6: pad.1@4079.99,4035 pad.1@5359.99,4675 U1.5 U3.11 | length 2094.4
  Top Layer w10: pad.1@4079.99,4035 4082.51,4037.52 U1.5 ; pad.1@5359.99,4675 5472.4,4675 U3.11
  Bottom Layer w10: pad.1@4079.99,4035 4094.99,4050 5234.99,4050 5359.99,4175 pad.1@5359.99,4675
RS485RX: H7.4 U4.1 | length 344.9
  Top Layer w10: H7.4 5629.99,3840 5729.99,3940 U4.1
RS485SW: H7.2 pad.1@5669.99,3940 pad.2@5779.99,3865 U4.2 U4.3 | length 385.8
  Top Layer w10: H7.2 pad.1@5669.99,3940 ; pad.2@5779.99,3865 5855.41,3865 5858.49,3861.92 ; U4.3 5858.49,3861.92 ; U4.2 5858.49,3861.92
  Bottom Layer w10: pad.1@5669.99,3940 5744.99,3865 pad.2@5779.99,3865
RS485TX: H7.6 U4.4 | length 324.2
  Top Layer w10: H7.6 5654.99,3740 5704.99,3790 U4.4
RST: C7.2 pad.1@3694.99,3445 pad.1@4259.99,4025 R2.1 RST1.2 U1.14 | length 2055
  Top Layer w10: RST1.2 3254.49,3220 3675.62,3220 C7.2 R2.1 pad.1@3694.99,3445 ; U1.14 4259.99,4177.45 pad.1@4259.99,4025
  Bottom Layer w10: pad.1@3694.99,3445 3694.99,3545 3749.99,3600 4079.99,3600 4259.99,3780 pad.1@4259.99,4025
VDDA: C15.1 C16.1 R35.2 R36.2 U1.22 | length 830
  Top Layer w10: U1.22 4417.16,4070 4507.16,3980 R36.2 4801.89,3976.26 R35.2
VREF+: C14.1 R35.1 U1.21 | length 1220.8
  Top Layer w10: U1.21 4397.48,4062.52 4504.99,3955 4639.99,3955 4739.99,3855 4739.99,3605 4764.99,3580 4874.99,3580 4882.07,3587.07 R35.1@4882.07,3683.56 ; R35.1 R35.1@4882.07,3683.56 ; C14.1 4884.36,3681.26 R35.1@4882.07,3683.56
pads on no net: R37.1 U1.94 USB1.4
copper on no net: | length 418.5
  Top Layer w10: 3589.36,4490 3629.99,4449.37 3629.99,4435 ; 3764.99,4355 3766.89,4356.89 3942.76,4356.89
  Bottom Layer w10: 3629.99,4435 3684.99,4435 3764.99,4355

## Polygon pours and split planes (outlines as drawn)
GND on Bottom Layer (solid, remove dead copper): 3019.99,3031.92 7254.99,3031.92 7254.99,5120 3019.99,5120

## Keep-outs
Board Outline Layer:
  lines w10: 3029.99,3020 7264.99,3020 7264.99,5120 3029.99,5120 3029.99,3020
